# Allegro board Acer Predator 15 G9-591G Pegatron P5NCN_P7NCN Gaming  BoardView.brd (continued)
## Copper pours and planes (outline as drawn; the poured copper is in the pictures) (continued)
N126075660 on BOTTOM (solid shape): 181.52,43.07 182.2,42.39 182.21,42.39 182.27,42.33 186.3,42.33 186.73,41.91 186.73,40.97 182.43,40.97 181.9,41.5 183.56,41.5 183.57,41.44 183.58,41.39 183.6,41.33 183.63,41.29 183.66,41.24 183.7,41.2 183.75,41.17 183.8,41.14 183.85,41.13 183.91,41.12 183.96,41.11 184.02,41.12 184.07,41.13 184.12,41.16 184.17,41.19 184.21,41.22 184.25,41.26 184.28,41.31 184.3,41.36 184.32,41.41 184.33,41.47 184.33,41.52 184.32,41.58 184.3,41.63 184.28,41.68 184.25,41.73 184.21,41.77 184.17,41.81 184.12,41.84 184.07,41.86 184.02,41.87 183.96,41.88 183.91,41.88 183.85,41.87 183.8,41.85 183.75,41.82 183.7,41.79 183.66,41.75 183.63,41.71 183.6,41.66 183.58,41.61 183.57,41.55 183.56,41.5 181.9,41.5 181.51,41.89 181.35,41.91 181.34,42.06 181.34,42.23 181.24,42.33 181.24,42.37 181.19,42.41 181.19,43.06 181.29,43.16 181.43,43.16
N126076879 on IN2 (solid shape): outline of 693 points within 170.18,39.03 182.17,43.76
N126273757 on TOP (solid shape): 24.71,133.71 24.71,133.29 24.68,133.26 23.07,133.26 22.98,133.35 22.98,133.77 23.06,133.85 24.57,133.85
N126612092 on TOP (solid shape): 241.11,89.97 241.11,89.11 241.2,89.02 242.77,89.02 242.82,88.97 242.82,88.17 242.7,88.04 239.84,88.04 239.5,88.38 239.5,89.83 239.79,90.13 240.94,90.13
N126721746 on BOTTOM (solid shape): 22.01,135.27 22.24,135.17 22.47,135.27 22.66,135.27 22.8,135.18 22.97,135.18 22.99,135.19 23.17,135.02 23.17,134.76 22.91,134.51 21.37,134.51 21.3,134.58 21.3,134.8 21.66,135.17 21.68,135.17 21.76,135.21 21.83,135.27
N126721910 on BOTTOM (solid shape): 22.91,135.68 22.97,135.61 23.04,135.56 23.04,135.4 22.95,135.31 22.89,135.3 22.84,135.3 22.56,135.44 22.28,135.3 22.24,135.3 22.19,135.3 21.91,135.44 21.63,135.3 21.54,135.3 21.3,135.05 20.83,135.05 20.75,135.14 20.75,135.43 21,135.68
N129634919 on BOTTOM (solid shape): 155.92,108.7 155.92,107.52 155.81,107.41 155.63,107.41 155.63,107.41 154.48,107.41 154.27,107.62 154.27,108.92 154.34,108.98 155.64,108.98
N129635970 on TOP (solid shape): 147.12,94.73 147.12,94.25 147.25,94.12 147.25,92.86 147.02,92.63 147.02,91.74 146.94,91.66 146.58,91.66 146.35,91.89 146.35,94.54 146.61,94.8 147.05,94.8
N129637628 on TOP (solid shape): 145.37,98.11 145.37,96.14 145.34,96.11 144.91,96.11 144.83,96.19 144.83,96.96 144.2,97.6 144.2,98.14 144.28,98.23 145.26,98.23
N129637680 on TOP (solid shape): 146.86,99.04 146.86,99.03 147.24,98.65 147.24,96.23 147.12,96.11 146.61,96.11 146.61,98.26 146.13,98.75 145.22,98.75 145.22,99.31 145.27,99.36 146.55,99.36
N129962530 on TOP (solid shape): 13.18,72.6 13.96,72.6 14.38,72.18 15,72.18 15.15,72.03 15.15,71.79 15,71.63 14.69,71.63 14.63,71.64 14.57,71.63 14.29,71.63 13.91,72.01 13.09,72.01 11.69,73.4 11.69,73.5 11.94,73.75 12.03,73.75
N129963384 on IN2 (solid shape): outline of 135 points within 15.55,64.76 18.14,67.71
N129963392 on TOP (solid shape): 18.82,66.95 18.82,66.34 18.78,66.29 18.78,65.78 18.62,65.51 18.71,65.22 18.73,65.15 18.71,65.08 18.67,65.03 18.64,64.97 18.64,64.09 19.41,64.53 20.12,64.53 20.13,64.5 20.71,64.37 20.72,64.96 20.68,65.04 20.71,65.11 20.83,65.24 20.83,65.32 20.84,65.33 20.85,65.44 20.84,65.54 20.83,65.55 20.83,65.65 20.59,65.89 20.59,66.97 20.76,66.97 20.81,66.91 20.81,66.25 21.33,65.73 21.33,61.63 20.88,61.18 17.49,61.18 17.49,64.14 17.68,64.14 18.28,64.74 18.28,65.68 18.53,65.94 18.53,66.27 18.6,66.34 18.6,66.91 18.66,66.97 18.8,66.97
N136259332 on TOP (solid shape): 249.83,41.6 249.83,40.2 249.48,39.84 247.6,39.84 246.71,38.96 246.71,38.3 246.63,38.22 246.46,38.22 246.38,38.3 246.38,38.32 246.32,38.51 246.14,38.6 246.12,38.6 246.08,38.65 246.08,38.89 246.09,38.9 246.09,39.22 246.43,39.83 246.43,41.52 246.58,41.67 249.76,41.67
N137261398 on TOP (solid shape): 251.8,82.99 252.64,82.99 252.86,82.77 252.86,80.76 252.65,80.56 250.37,80.56 250.34,80.59 247.6,80.59 247.19,80.99 247.19,81.75 247.44,82.01 250.34,82.01 250.5,82.17 250.54,82.19 250.58,82.17 251.12,82.17 251.12,82.71 251.1,82.75 251.12,82.78 251.33,83 251.79,83
N138435047 on TOP (solid shape): 186.41,81.27 186.41,80.46 187,79.87 187,79.09 186.94,79.03 185.34,79.03 185.17,79.21 185.17,81.19 185.29,81.32 186.36,81.32
N138949618 on BOTTOM (solid shape): 45.77,170.65 45.77,169.94 45.64,169.81 43.74,169.81 43.61,169.94 43.61,170.45 43.61,170.45 43.61,171.04 44.07,171.49 44.93,171.49
N138973270 on BOTTOM (solid shape): 32.31,169.69 31.73,169.11 30.84,169.11 30.67,169.27 30.67,169.68 30.66,169.69 30.66,170.96 32.31,170.96
N138993942 on TOP (solid shape): 63.55,164.43 63.55,163.29 63.3,163.03 61.52,163.03 61.49,163.06 60.99,163.06 60.78,163.26 60.78,163.95 60.93,164.1 62.59,164.1 63.04,164.56 63.42,164.56
N139012589 on TOP (solid shape): 2.08,157.88 2.46,157.49 3.48,157.49 3.48,156.86 3.35,156.73 1.32,156.73 1.19,156.86 1.19,158.64 1.45,158.89 2.08,158.89
N139027720 on BOTTOM (solid shape): 20.63,165.68 20.63,162.48 20.47,162.32 19.81,162.32 19.74,162.4 19.74,165.11 19.79,165.11 19.91,165.24 19.91,166.01 19.99,166.08 20.22,166.08
N139084693 on BOTTOM (solid shape): 68.31,171.59 68.31,169.79 68.35,169.75 68.35,169.25 68.26,169.15 67.9,169.15 67.85,169.21 67.85,169.48 67.84,169.49 67.84,169.79 67.83,169.8 67.83,171.53 67.89,171.59 68.3,171.59
N139090834 on BOTTOM (solid shape): 88.9,170.07 89.21,170.07 89.33,169.94 89.33,169.56 89.21,169.43 87.84,169.43 87.6,169.51 87.37,169.43 86.77,169.43 86.61,169.59 86.61,170.3 86.69,170.38 88.6,170.38
N140034678 on TOP (solid shape): 258.12,107.79 257.61,107.28 255.96,107.28 255.83,107.15 255.83,106.77 253.92,106.77 253.92,107.54 255.83,109.44 257.23,109.44 257.61,109.82 257.61,110.71 258.12,110.71
N145218678 on BOTTOM (solid shape): 224.82,52.85 224.82,51.67 224.96,51.53 224.96,49.31 224.89,49.24 223.68,49.24 223.46,49.46 223.46,50.33 222.67,51.12 222.67,52.75 222.8,52.89 224.78,52.89
N146002641 on TOP (solid shape): 51.38,182.87 51.38,181.89 51.38,181.47 51.38,181.47 51.38,180.8 51.14,180.8 51.13,180.81 51.13,181.9 51.12,181.9 50.88,181.9 50.88,181.9 50.88,180.8 50.64,180.8 50.64,182.83 50.76,182.96 51.29,182.96
N146002641 on BOTTOM (solid shape): 53.23,183.84 52.64,183.84 51.11,182.31 50.82,182.31 50.56,182.57 50.56,184.63 51.87,184.63 51.87,184.63 52.13,184.63 52.18,184.69 53.23,184.69

Small or netless copper shapes (teardrops, artwork), in the pictures only: 4158 on TOP, 5851 on BOTTOM, 1031 on IN1, 539 on IN2, 141 on IN3, 900 on IN4

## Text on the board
BOTTOM: list("[Spacing] BOTTOM" "164.Shape to Route Keepin" "0 MIL [DEFAULT]" "0 MIL" "0.00 MIL" "DRC ERROR CLASS/BOTTOM" "[Shape] Route Keepin/All ((-917.01 -373.7) (9771.34 6936.7))" "[Bottom Shape] GND ((-917.01 -373.7) (9771.34 6944.68))" list(118.110000 -373.700000) nil)@@@list("kelly1_pan" "2015/09/04 14:26:33" nil "P143000035-PC" "n3-p5-p7ncn.20")@@@list("jennifer_hsu" "2015/09/07 11:46:35" nil "P143000039-PC" "n3-p5-p7ncn.20") | list("[Spacing] BOTTOM" "166.Line to SMD Pin" "4.5 MIL [DEFAULT]" "4.4 MIL" "0.10 MIL" "DRC ERROR CLASS/BOTTOM" "[Line] LP9- ((1166.4 6673.51) (1170.9 6752.69))" "[SmdPin] GND (<uTiL>cId3016<uTiL>.2) (1150.0 6724.01)" list(1168.650000 6724.010000) nil)@@@list("kelly1_pan" "2015/09/04 14:26:36" nil "P143000035-PC" "n3-p5-p7ncn.20")@@@list("jennifer_hsu" "2015/09/07 11:46:36" nil "P143000039-PC" "n3-p5-p7ncn.20") | list("[Spacing] BOTTOM" "165.Shape to Route Keepout" "0 MIL [DEFAULT]" "0 MIL" "0.00 MIL" "DRC ERROR CLASS/BOTTOM" "[Shape] Route Keepout/Bottom ((4840.37 356.11) (5175.37 691.11))" "[Bottom Shape] GND ((-917.01 -373.7) (9771.34 6944.68))" list(4906.130000 390.550000) nil)@@@list("kelly1_pan" "2015/09/04 14:26:34" nil "P143000035-PC" "n3-p5-p7ncn.20")@@@list("jennifer_hsu" "2015/09/07 11:46:35" nil "P143000039-PC" "n3-p5-p7ncn.20") | list("[Spacing-SameNet] BOTTOM" "168.Line to Shape Same Net" "5 MIL [DEFAULT]" "0 MIL" "5.00 MIL" "DRC ERROR CLASS/BOTTOM" "[Line] GND ((5340.2 1970.8) (5365.89 1975.8))" "[Bottom Shape] GND ((4986.0 1241.89) (6155.0 2348.1))" list(5358.460000 1973.300000) nil)@@@list("kelly1_pan" "2015/09/04 14:26:38" nil "P143000035-PC" "n3-p5-p7ncn.20")@@@list("jennifer_hsu" "2015/09/07 11:46:38" nil "P143000039-PC" "n3-p5-p7ncn.20") | list("[Spacing] BOTTOM" "161.Shape to Route Keepin" "0 MIL [DEFAULT]" "0 MIL" "0.00 MIL" "DRC ERROR CLASS/BOTTOM" "[Shape] Route Keepin/All ((-917.01 -373.7) (9771.34 6936.7))" "[Bottom Shape] GND_LED ((5460.95 5728.54) (7231.95 6039.17))" list(5460.950000 5736.540000) nil)@@@list("kelly1_pan" "2015/09/04 14:26:30" nil "P143000035-PC" "n3-p5-p7ncn.20")@@@list("jennifer_hsu" "2015/09/07 11:46:33" nil "P143000039-PC" "n3-p5-p7ncn.20") | list("[Spacing] BOTTOM" "162.Shape to Route Keepin" "0 MIL [DEFAULT]" "0 MIL" "0.00 MIL" "DRC ERROR CLASS/BOTTOM" "[Shape] Route Keepin/All ((-917.01 -373.7) (9771.34 6936.7))" "[Bottom Shape] LAN_GND ((9292.77 4683.0) (9698.5 5486.88))" list(9332.360000 5367.300000) nil)@@@list("kelly1_pan" "2015/09/04 14:26:31" nil "P143000035-PC" "n3-p5-p7ncn.20")@@@list("jennifer_hsu" "2015/09/07 11:46:33" nil "P143000039-PC" "n3-p5-p7ncn.20") | list("[Spacing] BOTTOM" "163.Shape to Route Keepin" "0 MIL [DEFAULT]" "0 MIL" "0.00 MIL" "DRC ERROR CLASS/BOTTOM" "[Shape] Route Keepin/All ((-917.01 -373.7) (9771.34 6936.7))" "[Bottom Shape] GND ((9278.0 1449.01) (9668.98 2197.11))" list(9367.790000 1452.900000) nil)@@@list("kelly1_pan" "2015/09/04 14:26:32" nil "P143000035-PC" "n3-p5-p7ncn.20")@@@list("jennifer_hsu" "2015/09/07 11:46:34" nil "P143000039-PC" "n3-p5-p7ncn.20") | list("[Spacing] BOTTOM" "167.Shape to Route Keepin" "0 MIL [DEFAULT]" "0 MIL" "0.00 MIL" "DRC ERROR CLASS/BOTTOM" "[Shape] Route Keepin/All ((-917.01 -373.7) (9771.34 6936.7))" "[Bottom Shape] GND ((9336.61 1757.88) (9671.25 2092.52))" list(9668.980000 1757.880000) nil)@@@list("kelly1_pan" "2015/09/04 14:26:37" nil "P143000035-PC" "n3-p5-p7ncn.20")@@@list("jennifer_hsu" "2015/09/07 11:46:37" nil "P143000039-PC" "n3-p5-p7ncn.20")
Ref Des/Silkscreen Bottom: CON5602 | PCB MADE IN | BOT | CON6701 | XDP4400 | CON3600 | H64 | CON5000 | CON6003 | CON1601 | CON1701 | CON5103 | H61 | H66 | CON5102 | JP9401 | JP9400 | CON4400 | H65 | H63 | CON3100 | U7000 | H60 | CON3110 | H69 | H68 | JP8200 | U2000 | JP8901 | REV:2.0 | _DMIC_L | P/N: | P5NCN/P7NCN | CON3104 | CON5001 | CON3700 | JP8105 | CON4402 | P5NCN/P7NCN_DMIC_R BD | JP9302 | JP9301 | CON6000 | CON5300 | H62 | CON6002 | H34 | H33 | CON3400 | CON2800 | H701 | H702 | CON6700 | CON6001 | CON5101 | CON5100 | JP8061 | JP8056 | JP8103 | JP8104 | vendor | 2ND
TOP: list("[Spacing] TOP" "11.Shape to Route Keepout" "0 MIL [DEFAULT]" "0 MIL" "0.00 MIL" "DRC ERROR CLASS/TOP" "[Shape] Route Keepout/Top ((-195.82 1247.95) (60.4 1504.09))" "[Top Shape] GND ((-917.01 -373.69) (9771.72 6944.68))" list(-63.220000 1247.950000) nil)@@@list("kelly1_pan" "2015/09/02 11:47:46" nil "P143000035-PC" "n3-p5-p7ncn.20")@@@list("jennifer_hsu" "2015/09/07 11:44:02" nil "P143000039-PC" "n3-p5-p7ncn.20") | list("[Spacing] TOP" "10.Shape to Route Keepout" "0 MIL [DEFAULT]" "0 MIL" "0.00 MIL" "DRC ERROR CLASS/TOP" "[Shape] Route Keepout/Top ((-195.82 145.51) (60.4 401.69))" "[Top Shape] GND ((-917.01 -373.69) (9771.72 6944.68))" list(-52.150000 400.780000) nil)@@@list("kelly1_pan" "2015/09/02 11:47:45" nil "P143000035-PC" "n3-p5-p7ncn.20")@@@list("jennifer_hsu" "2015/09/07 11:44:02" nil "P143000039-PC" "n3-p5-p7ncn.20") | list("[Spacing] TOP" "9.Shape to Route Keepin" "0 MIL [DEFAULT]" "0 MIL" "0.00 MIL" "DRC ERROR CLASS/TOP" "[Shape] Route Keepin/All ((-917.01 -373.7) (9771.34 6936.7))" "[Top Shape] GND ((-917.01 -373.69) (9771.72 6944.68))" list(137.480000 381.890000) nil)@@@list("kelly1_pan" "2015/09/02 11:47:44" nil "P143000035-PC" "n3-p5-p7ncn.20")@@@list("jennifer_hsu" "2015/09/07 11:44:01" nil "P143000039-PC" "n3-p5-p7ncn.20") | list("[Spacing] TOP" "15.SMD Pin to SMD Pin Same Net" "3 MIL [DEFAULT]" "OVERLAP" "" "DRC ERROR CLASS/TOP" "[SmdPin] +VCORE (<uTiL>cId1632<uTiL>.2) (489.09 6106.89)" "[SmdPin] +VCORE (<uTiL>cId3931<uTiL>.2) (442.2 6143.49)" list(442.590000 6130.990000) nil)@@@list("kelly1_pan" "2015/09/02 11:47:50" nil "P143000035-PC" "n3-p5-p7ncn.20")@@@list("jennifer_hsu" "2015/09/07 11:44:06" nil "P143000039-PC" "n3-p5-p7ncn.20") | list("[Spacing] TOP" "4.Shape to Route Keepout" "0 MIL [DEFAULT]" "0 MIL" "0.00 MIL" "DRC ERROR CLASS/TOP" "[Shape] Route Keepout/Top ((3271.29 2635.46) (3567.29 2931.46))" "[Top Shape] GND ((3336.7 2521.89) (4319.2 3000.94))" list(3345.800000 2654.990000) nil)@@@list("kelly1_pan" "2015/09/02 11:47:41" nil "P143000035-PC" "n3-p5-p7ncn.20")@@@list("jennifer_hsu" "2015/09/07 11:43:57" nil "P143000039-PC" "n3-p5-p7ncn.20") | list("[Spacing] TOP" "12.SMD Pin to SMD Pin Same Net" "3 MIL [DEFAULT]" "0 MIL" "3.00 MIL" "DRC ERROR CLASS/TOP" "[SmdPin] +2.5VO (<uTiL>cId3914<uTiL>.2) (3467.0 2161.89)" "[SmdPin] +2.5VO (<uTiL>cId3915<uTiL>.2) (3450.0 2173.89)" list(3462.500000 2171.890000) nil)@@@list("kelly1_pan" "2015/09/02 11:47:47" nil "P143000035-PC" "n3-p5-p7ncn.20")@@@list("jennifer_hsu" "2015/09/07 11:44:03" nil "P143000039-PC" "n3-p5-p7ncn.20") | list("[Spacing] TOP" "13.SMD Pin to SMD Pin Same Net" "3 MIL [DEFAULT]" "0 MIL" "3.00 MIL" "DRC ERROR CLASS/TOP" "[SmdPin] +1.2VO_DDR (<uTiL>cId3922<uTiL>.1) (3671.0 2328.89)" "[SmdPin] +1.2VO_DDR (<uTiL>cId3921<uTiL>.1) (3688.0 2335.89)" list(3683.500000 2328.890000) nil)@@@list("kelly1_pan" "2015/09/02 11:47:48" nil "P143000035-PC" "n3-p5-p7ncn.20")@@@list("jennifer_hsu" "2015/09/07 11:44:04" nil "P143000039-PC" "n3-p5-p7ncn.20") | list("[Spacing] TOP" "14.SMD Pin to SMD Pin Same Net" "3 MIL [DEFAULT]" "OVERLAP" "" "DRC ERROR CLASS/TOP" "[SmdPin] +0.6VO (<uTiL>cId4502<uTiL>.1) (4243.62 1911.89)" "[SmdPin] +0.6VO (<uTiL>cId1706<uTiL>.1) (4256.0 1909.0)" list(4254.620000 1896.500000) nil)@@@list("kelly1_pan" "2015/09/02 11:47:49" nil "P143000035-PC" "n3-p5-p7ncn.20")@@@list("jennifer_hsu" "2015/09/07 11:44:05" nil "P143000039-PC" "n3-p5-p7ncn.20") | list("[Spacing] TOP" "2.Shape to Route Keepin" "0 MIL [DEFAULT]" "0 MIL" "0.00 MIL" "DRC ERROR CLASS/TOP" "[Shape] Route Keepin/All ((-917.01 -373.7) (9771.34 6936.7))" "[Top Shape] GND_LED ((5460.95 5728.54) (7231.95 6031.17))" list(5552.560000 5736.540000) nil)@@@list("kelly1_pan" "2015/09/02 11:47:39" nil "P143000035-PC" "n3-p5-p7ncn.20")@@@list("jennifer_hsu" "2015/09/07 11:43:55" nil "P143000039-PC" "n3-p5-p7ncn.20") | list("[Spacing] TOP" "1.Shape to Route Keepin" "0 MIL [DEFAULT]" "0 MIL" "0.00 MIL" "DRC ERROR CLASS/TOP" "[Shape] Route Keepin/All ((-917.01 -373.7) (9771.34 6936.7))" "[Top Shape] GND_D-MIC R ((6567.24 5303.46) (7357.95 5617.79))" list(6586.610000 5303.470000) nil)@@@list("kelly1_pan" "2015/09/02 11:47:38" nil "P143000035-PC" "n3-p5-p7ncn.20")@@@list("jennifer_hsu" "2015/09/07 11:43:55" nil "P143000039-PC" "n3-p5-p7ncn.20") | list("[Physical] TOP" "94.Pad/Pad Direct Connect" "NOT_ALLOWED [(GND_20)]" "ALL_ALLOWED" "" "DRC ERROR CLASS/TOP" "[ThruPin] GND (<uTiL>cId2974<uTiL>.49) (8093.66 3281.89)" "[SmdPin] GND (<uTiL>cId2974<uTiL>.41) (8035.0 3281.89)" list(8093.660000 3281.890000) nil)@@@list("kelly1_pan" "2015/09/04 14:26:39" nil "P143000035-PC" "n3-p5-p7ncn.20")@@@nil | list("[Spacing] TOP" "3.Shape to Route Keepin" "0 MIL [DEFAULT]" "0 MIL" "0.00 MIL" "DRC ERROR CLASS/TOP" "[Shape] Route Keepin/All ((-917.01 -373.7) (9771.34 6936.7))" "[Top Shape] LAN_GND ((9292.76 4683.0) (9698.5 5486.88))" list(9332.360000 5367.300000) nil)@@@list("kelly1_pan" "2015/09/02 11:47:40" nil "P143000035-PC" "n3-p5-p7ncn.20")@@@list("jennifer_hsu" "2015/09/07 11:43:56" nil "P143000039-PC" "n3-p5-p7ncn.20") | list("[Spacing] TOP" "5.Shape to Route Keepin" "0 MIL [DEFAULT]" "0 MIL" "0.00 MIL" "DRC ERROR CLASS/TOP" "[Shape] Route Keepin/All ((-917.01 -373.7) (9771.34 6936.7))" "[Top Shape] GND ((9319.8 2527.75) (9367.8 2695.57))" list(9367.790000 2691.850000) nil)@@@list("kelly1_pan" "2015/09/02 11:47:42" nil "P143000035-PC" "n3-p5-p7ncn.20")@@@list("jennifer_hsu" "2015/09/07 11:43:58" nil "P143000039-PC" "n3-p5-p7ncn.20") | list("[Spacing] TOP" "8.Shape to Route Keepin" "0 MIL [DEFAULT]" "0 MIL" "0.00 MIL" "DRC ERROR CLASS/TOP" "[Shape] Route Keepin/All ((-917.01 -373.7) (9771.34 6936.7))" "[Top Shape] GND ((9250.3 1449.01) (9668.97 2197.18))" list(9368.830000 1660.590000) nil)@@@list("kelly1_pan" "2015/09/02 11:46:52" nil "P143000035-PC" "n3-p5-p7ncn.20")@@@list("jennifer_hsu" "2015/09/07 11:44:00" nil "P143000039-PC" "n3-p5-p7ncn.20") | list("[Spacing] TOP" "6.Shape to Route Keepout" "0 MIL [DEFAULT]" "0 MIL" "0.00 MIL" "DRC ERROR CLASS/TOP" "[Shape] Route Keepout/All ((-937.01 -393.7) (9791.34 6956.69))" "[Top Shape] GND ((9251.0 2737.09) (9698.51 4686.9))" list(9676.990000 2758.030000) nil)@@@list("kelly1_pan" "2015/09/02 11:47:07" nil "P143000035-PC" "n3-p5-p7ncn.20")@@@list("jennifer_hsu" "2015/09/07 11:43:58" nil "P143000039-PC" "n3-p5-p7ncn.20") | list("[Spacing] TOP" "7.Shape to Route Keepin" "0 MIL [DEFAULT]" "0 MIL" "0.00 MIL" "DRC ERROR CLASS/TOP" "[Shape] Route Keepin/All ((-917.01 -373.7) (9771.34 6936.7))" "[Top Shape] GND ((9251.0 2737.09) (9698.51 4686.9))" list(9688.980000 2770.050000) nil)@@@list("kelly1_pan" "2015/09/02 11:47:08" nil "P143000035-PC" "n3-p5-p7ncn.20")@@@list("jennifer_hsu" "2015/09/07 11:43:59" nil "P143000039-PC" "n3-p5-p7ncn.20")
Ref Des/Silkscreen Top: JP9601 | JP9600 | REV:2.0 | CON1 | P5NCN/P7NCN_LED BD | TOP | JP8802 | JP8801 | JP9300 | JP8806 | JP8059 | JP8060 | CON1600 | CON1700 | JP8055 | JP8054 | CON4500 | CON4301 | JP9500 | JP9501 | JP8304 | JP8303 | JP8301 | JP9000 | JP8300 | JP8202 | JP8902 | JP8400 | PCON700 | CON300 | H301 | CON402 | P5NCN/P7NCN_PWR BOARD | PCB MADE IN | CON400 | PCON702 | JP8109 | JP8102 | JP8108 | JP8106 | JP9303 | JP8100 | JP8101 | JP8110 | JP8111 | JP8800 | JP8803 | H402 | JP8058 | JP8057 | JP8052 | JP8053 | JP8051 | JP8050 | JP9602 | JP8302 | JP9502 | CON302 | JP8804 | JP8805 | JP8107 | CON4601 | CON5501 | CON5500 | CON4800 | CON1201 | JP5601 | H53 | H54 | 2015/9/7 | 2.0/650  mils | P5NCN/P7NCN MAIN BOARD | 1ST
GND1: list("[Spacing] GND1" "29.Thru Pin to Shape" "5 MIL [DEFAULT]" "4.99 MIL" "0.01 MIL" "DRC ERROR CLASS/GND1" "[ThruPin] GND (<uTiL>cId65<uTiL>.50) (-256.51 2263.3)" "[Gnd1 Shape] AGND ((-610.0 2155.0) (-65.0 2696.89))" list(-265.000000 2254.810000) nil)@@@list("kelly1_pan" "2015/09/02 15:29:40" nil "p143000035-pc" "n3-p5-p7ncn.20")@@@list("jennifer_hsu" "2015/09/07 11:44:30" nil "P143000039-PC" "n3-p5-p7ncn.20") | list("[Spacing] GND1" "19.Thru Pin to Shape Same Net" "5 MIL [DEFAULT]" "0 MIL" "5.00 MIL" "DRC ERROR CLASS/GND1" "[ThruPin] GND (<uTiL>cId65<uTiL>.50) (-256.51 2263.3)" "[Gnd1 Shape] GND ((-917.01 -373.7) (9771.34 6936.7))" list(-255.000000 2275.200000) nil)@@@list("kelly1_pan" "2015/09/02 15:29:31" nil "p143000035-pc" "n3-p5-p7ncn.20")@@@list("jennifer_hsu" "2015/09/07 11:44:09" nil "P143000039-PC" "n3-p5-p7ncn.20") | list("[Spacing] GND1" "20.Thru Pin to Shape Same Net" "5 MIL [DEFAULT]" "0 MIL" "5.00 MIL" "DRC ERROR CLASS/GND1" "[ThruPin] GND (<uTiL>cId65<uTiL>.51) (-256.51 2422.28)" "[Gnd1 Shape] GND ((-917.01 -373.7) (9771.34 6936.7))" list(-249.320000 2431.890000) nil)@@@list("kelly1_pan" "2015/09/02 15:29:32" nil "p143000035-pc" "n3-p5-p7ncn.20")@@@list("jennifer_hsu" "2015/09/07 11:44:09" nil "P143000039-PC" "n3-p5-p7ncn.20") | list("[Spacing] GND1" "22.Shape to Route Keepout" "0 MIL [DEFAULT]" "0 MIL" "0.00 MIL" "DRC ERROR CLASS/GND1" "[Shape] Route Keepout/All ((-133.59 333.73) (-56.95 410.36))" "[Gnd1 Shape] GND ((-917.01 -373.7) (9771.34 6936.7))" list(-95.270000 410.360000) nil)@@@list("kelly1_pan" "2015/09/02 15:29:34" nil "p143000035-pc" "n3-p5-p7ncn.20")@@@list("jennifer_hsu" "2015/09/07 11:44:11" nil "P143000039-PC" "n3-p5-p7ncn.20") | list("[Spacing] GND1" "21.Shape to Route Keepout" "0 MIL [DEFAULT]" "0 MIL" "0.00 MIL" "DRC ERROR CLASS/GND1" "[Shape] Route Keepout/All ((-123.21 218.12) (-12.21 329.12))" "[Gnd1 Shape] GND ((-917.01 -373.7) (9771.34 6936.7))" list(-67.710000 329.120000) nil)@@@list("kelly1_pan" "2015/09/02 15:29:33" nil "p143000035-pc" "n3-p5-p7ncn.20")@@@list("jennifer_hsu" "2015/09/07 11:44:10" nil "P143000039-PC" "n3-p5-p7ncn.20") | list("[Spacing] GND1" "26.Shape to Route Keepout" "0 MIL [DEFAULT]" "0 MIL" "0.00 MIL" "DRC ERROR CLASS/GND1" "[Shape] Route Keepout/All ((1831.32 6634.59) (1885.01 6688.27))" "[Gnd1 Shape] GND ((-917.01 -373.7) (9771.34 6936.7))" list(1885.010000 6661.430000) nil)@@@list("kelly1_pan" "2015/09/02 15:29:37" nil "p143000035-pc" "n3-p5-p7ncn.20")@@@list("jennifer_hsu" "2015/09/07 11:44:13" nil "P143000039-PC" "n3-p5-p7ncn.20") | list("[Spacing] GND1" "27.Shape to Route Keepout" "0 MIL [DEFAULT]" "0 MIL" "0.00 MIL" "DRC ERROR CLASS/GND1" "[Shape] Route Keepout/All ((3022.0 6798.93) (3081.62 6858.55))" "[Gnd1 Shape] GND ((-917.01 -373.7) (9771.34 6936.7))" list(3051.810000 6858.550000) nil)@@@list("kelly1_pan" "2015/09/02 15:29:37" nil "p143000035-pc" "n3-p5-p7ncn.20")@@@list("jennifer_hsu" "2015/09/07 11:44:14" nil "P143000039-PC" "n3-p5-p7ncn.20") | list("[Spacing] GND1" "16.Shape to Route Keepin" "0 MIL [DEFAULT]" "0 MIL" "0.00 MIL" "DRC ERROR CLASS/GND1" "[Shape] Route Keepin/All ((-917.01 -373.7) (9771.34 6936.7))" "[Gnd1 Shape] GND_D-MIC R ((6567.24 5303.47) (7357.95 5617.8))" list(6869.960000 5617.800000) nil)@@@list("kelly1_pan" "2015/09/02 15:32:45" nil "P143000035-PC" "n3-p5-p7ncn.20")@@@list("jennifer_hsu" "2015/09/07 11:44:06" nil "P143000039-PC" "n3-p5-p7ncn.20") | list("[Spacing] GND1" "24.Shape to Route Keepout" "0 MIL [DEFAULT]" "0 MIL" "0.00 MIL" "DRC ERROR CLASS/GND1" "[Shape] Route Keepout/All ((8281.64 3112.35) (8348.26 3178.97))" "[Gnd1 Shape] GND ((-917.01 -373.7) (9771.34 6936.7))" list(8348.260000 3145.660000) nil)@@@list("kelly1_pan" "2015/09/02 15:29:35" nil "p143000035-pc" "n3-p5-p7ncn.20")@@@list("jennifer_hsu" "2015/09/07 11:44:12" nil "P143000039-PC" "n3-p5-p7ncn.20") | list("[Spacing] GND1" "23.Shape to Route Keepout" "0 MIL [DEFAULT]" "0 MIL" "0.00 MIL" "DRC ERROR CLASS/GND1" "[Shape] Route Keepout/All ((8396.75 1692.04) (8469.37 1764.66))" "[Gnd1 Shape] GND ((-917.01 -373.7) (9771.34 6936.7))" list(8469.370000 1728.350000) nil)@@@list("kelly1_pan" "2015/09/02 15:29:34" nil "p143000035-pc" "n3-p5-p7ncn.20")@@@list("jennifer_hsu" "2015/09/07 11:44:11" nil "P143000039-PC" "n3-p5-p7ncn.20") | list("[Spacing] GND1" "25.Shape to Route Keepout" "0 MIL [DEFAULT]" "0 MIL" "0.00 MIL" "DRC ERROR CLASS/GND1" "[Shape] Route Keepout/All ((8775.0 4660.0) (9725.0 5506.4))" "[Gnd1 Shape] GND ((-917.01 -373.7) (9771.34 6936.7))" list(9252.800000 4689.950000) nil)@@@list("kelly1_pan" "2015/09/02 15:29:36" nil "p143000035-pc" "n3-p5-p7ncn.20")@@@list("jennifer_hsu" "2015/09/07 11:44:13" nil "P143000039-PC" "n3-p5-p7ncn.20") | list("[Spacing] GND1" "17.Shape to Route Keepout" "0 MIL [DEFAULT]" "0 MIL" "0.00 MIL" "DRC ERROR CLASS/GND1" "[Shape] Route Keepout/All ((8775.0 4660.0) (9725.0 5506.4))" "[Gnd1 Shape] LAN_GND ((8795.0 4680.0) (9698.5 5487.0))" list(9289.360000 4680.000000) nil)@@@list("kelly1_pan" "2015/09/02 15:29:29" nil "p143000035-pc" "n3-p5-p7ncn.20")@@@list("jennifer_hsu" "2015/09/07 11:44:07" nil "P143000039-PC" "n3-p5-p7ncn.20") | list("[Spacing] GND1" "18.Shape to Route Keepin" "0 MIL [DEFAULT]" "0 MIL" "0.00 MIL" "DRC ERROR CLASS/GND1" "[Shape] Route Keepin/All ((-917.01 -373.7) (9771.34 6936.7))" "[Gnd1 Shape] LAN_GND ((8795.0 4680.0) (9698.5 5487.0))" list(9386.640000 5421.580000) nil)@@@list("kelly1_pan" "2015/09/02 15:29:30" nil "p143000035-pc" "n3-p5-p7ncn.20")@@@list("jennifer_hsu" "2015/09/07 11:44:08" nil "P143000039-PC" "n3-p5-p7ncn.20") | list("[Spacing] GND1" "28.Shape to Route Keepin" "0 MIL [DEFAULT]" "0 MIL" "0.00 MIL" "DRC ERROR CLASS/GND1" "[Shape] Route Keepin/All ((-917.01 -373.7) (9771.34 6936.7))" "[Gnd1 Shape] GND ((-917.01 -373.7) (9771.34 6936.7))" list(9433.500000 4571.180000) nil)@@@list("kelly1_pan" "2015/09/02 15:29:38" nil "p143000035-pc" "n3-p5-p7ncn.20")@@@list("jennifer_hsu" "2015/09/07 11:44:14" nil "P143000039-PC" "n3-p5-p7ncn.20")
IN1: list("[Spacing] IN1" "35.Shape to Route Keepin" "0 MIL [DEFAULT]" "0 MIL" "0.00 MIL" "DRC ERROR CLASS/IN1" "[Shape] Route Keepin/All ((-917.01 -373.7) (9771.34 6936.7))" "[In1 Shape] GND ((-137.47 -373.69) (9771.34 1219.0))" list(137.480000 381.890000) nil)@@@list("kelly1_pan" "2015/09/02 15:32:58" nil "P143000035-PC" "n3-p5-p7ncn.20")@@@list("jennifer_hsu" "2015/09/07 11:44:35" nil "P143000039-PC" "n3-p5-p7ncn.20") | list("[Spacing] IN1" "30.Shape to Route Keepin" "0 MIL [DEFAULT]" "0 MIL" "0.00 MIL" "DRC ERROR CLASS/IN1" "[Shape] Route Keepin/All ((-917.01 -373.7) (9771.34 6936.7))" "[In1 Shape] GND_LED ((5460.94 5736.53) (7231.96 6031.18))" list(6260.100000 5736.540000) nil)@@@list("kelly1_pan" "2015/09/02 15:32:47" nil "P143000035-PC" "n3-p5-p7ncn.20")@@@list("jennifer_hsu" "2015/09/07 11:44:31" nil "P143000039-PC" "n3-p5-p7ncn.20") | list("[Spacing] IN1" "36.Shape to Route Keepin" "0 MIL [DEFAULT]" "0 MIL" "0.00 MIL" "DRC ERROR CLASS/IN1" "[Shape] Route Keepin/All ((-917.01 -373.7) (9771.34 6936.7))" "[In1 Shape] GND ((-917.0 1327.0) (9698.51 6936.7))" list(6742.230000 2896.930000) nil)@@@list("kelly1_pan" "2015/09/02 15:32:59" nil "P143000035-PC" "n3-p5-p7ncn.20")@@@list("jennifer_hsu" "2015/09/07 11:44:36" nil "P143000039-PC" "n3-p5-p7ncn.20") | list("[Spacing] IN1" "31.Shape to Route Keepin" "0 MIL [DEFAULT]" "0 MIL" "0.00 MIL" "DRC ERROR CLASS/IN1" "[Shape] Route Keepin/All ((-917.01 -373.7) (9771.34 6936.7))" "[In1 Shape] LAN_GND ((9292.77 4680.51) (9698.51 5486.88))" list(9332.360000 5367.300000) nil)@@@list("kelly1_pan" "2015/09/02 15:32:48" nil "P143000035-PC" "n3-p5-p7ncn.20")@@@list("jennifer_hsu" "2015/09/07 11:44:32" nil "P143000039-PC" "n3-p5-p7ncn.20") | list("[Spacing] IN1" "34.Shape to Route Keepin" "0 MIL [DEFAULT]" "0 MIL" "0.00 MIL" "DRC ERROR CLASS/IN1" "[Shape] Route Keepin/All ((-917.01 -373.7) (9771.34 6936.7))" "[In1 Shape] GND ((9268.0 1129.54) (9367.8 1626.71))" list(9367.790000 1396.470000) nil)@@@list("kelly1_pan" "2015/09/02 15:32:49" nil "P143000035-PC" "n3-p5-p7ncn.20")@@@list("jennifer_hsu" "2015/09/07 11:44:35" nil "P143000039-PC" "n3-p5-p7ncn.20") | list("[Spacing] IN1" "32.Shape to Route Keepin" "0 MIL [DEFAULT]" "0 MIL" "0.00 MIL" "DRC ERROR CLASS/IN1" "[Shape] Route Keepin/All ((-917.01 -373.7) (9771.34 6936.7))" "[In1 Shape] GND ((9210.0 1653.11) (9698.5 3131.17))" list(9368.840000 1660.640000) nil)@@@list("kelly1_pan" "2015/09/02 15:32:50" nil "P143000035-PC" "n3-p5-p7ncn.20")@@@list("jennifer_hsu" "2015/09/07 11:44:33" nil "P143000039-PC" "n3-p5-p7ncn.20") | list("[Spacing] IN1" "33.Shape to Route Keepout" "0 MIL [DEFAULT]" "0 MIL" "0.00 MIL" "DRC ERROR CLASS/IN1" "[Shape] Route Keepout/All ((-937.01 -393.7) (9791.34 6956.69))" "[In1 Shape] GND ((9210.0 1653.11) (9698.5 3131.17))" list(9676.990000 2758.020000) nil)@@@list("kelly1_pan" "2015/09/02 15:32:57" nil "P143000035-PC" "n3-p5-p7ncn.20")@@@list("jennifer_hsu" "2015/09/07 11:44:34" nil "P143000039-PC" "n3-p5-p7ncn.20") | list("[Spacing] IN1" "38.Shape to Route Keepout" "0 MIL [DEFAULT]" "0 MIL" "0.00 MIL" "DRC ERROR CLASS/IN1" "[Shape] Route Keepout/All ((9655.0 4660.5) (9762.0 4680.5))" "[In1 Shape] GND ((-917.0 1327.0) (9698.51 6936.7))" list(9678.600000 4660.500000) nil)@@@list("kelly1_pan" "2015/09/02 15:33:01" nil "P143000035-PC" "n3-p5-p7ncn.20")@@@list("jennifer_hsu" "2015/09/07 11:44:38" nil "P143000039-PC" "n3-p5-p7ncn.20") | list("[Spacing] IN1" "37.Shape to Route Keepout" "0 MIL [DEFAULT]" "0 MIL" "0.00 MIL" "DRC ERROR CLASS/IN1" "[Shape] Route Keepout/All ((8775.0 4660.0) (9725.0 5506.4))" "[In1 Shape] GND ((-917.0 1327.0) (9698.51 6936.7))" list(9678.600000 4660.000000) nil)@@@list("kelly1_pan" "2015/09/02 15:33:00" nil "P143000035-PC" "n3-p5-p7ncn.20")@@@list("jennifer_hsu" "2015/09/07 11:44:37" nil "P143000039-PC" "n3-p5-p7ncn.20")
GND2: list("[Spacing] GND2" "75.Shape to Route Keepout" "0 MIL [DEFAULT]" "0 MIL" "0.00 MIL" "DRC ERROR CLASS/GND2" "[Shape] Route Keepout/All ((-831.77 4457.88) (-768.15 4521.5))" "[Gnd2 Shape] +AC_BAT_SYS ((-885.0 1165.0) (230.0 6905.0))" list(-830.000000 4500.150000) nil)@@@list("kelly1_pan" "2015/09/02 15:36:58" nil "P143000035-PC" "n3-p5-p7ncn.20")@@@list("jennifer_hsu" "2015/09/07 11:45:20" nil "P143000039-PC" "n3-p5-p7ncn.20") | list("[Spacing] GND2" "71.Shape to Route Keepout" "0 MIL [DEFAULT]" "0 MIL" "0.00 MIL" "DRC ERROR CLASS/GND2" "[Shape] Route Keepout/All ((-831.77 4457.88) (-768.15 4521.5))" "[Gnd2 Shape] GND ((-917.01 -373.7) (9771.34 6936.7))" list(-768.150000 4489.690000) nil)@@@list("kelly1_pan" "2015/09/02 15:33:33" nil "P143000035-PC" "n3-p5-p7ncn.20")@@@list("jennifer_hsu" "2015/09/07 11:45:08" nil "P143000039-PC" "n3-p5-p7ncn.20") | list("[Spacing] GND2" "85.Thru Pin to Shape" "5 MIL [DEFAULT]" "4.99 MIL" "0.01 MIL" "DRC ERROR CLASS/GND2" "[ThruPin] GND (<uTiL>cId65<uTiL>.50) (-256.51 2263.3)" "[Gnd2 Shape] AGND ((-610.0 2155.0) (-65.0 2696.89))" list(-265.000000 2254.810000) nil)@@@list("kelly1_pan" "2015/09/04 14:25:19" nil "P143000035-PC" "n3-p5-p7ncn.20")@@@list("jennifer_hsu" "2015/09/07 11:45:30" nil "P143000039-PC" "n3-p5-p7ncn.20") | list("[Spacing] GND2" "42.Thru Pin to Shape Same Net" "5 MIL [DEFAULT]" "0 MIL" "5.00 MIL" "DRC ERROR CLASS/GND2" "[ThruPin] GND (<uTiL>cId65<uTiL>.50) (-256.51 2263.3)" "[Gnd2 Shape] GND ((-917.01 -373.7) (9771.34 6936.7))" list(-255.000000 2275.200000) nil)@@@list("kelly1_pan" "2015/09/02 15:33:05" nil "P143000035-PC" "n3-p5-p7ncn.20")@@@list("jennifer_hsu" "2015/09/07 11:44:40" nil "P143000039-PC" "n3-p5-p7ncn.20") | list("[Spacing] GND2" "43.Thru Pin to Shape Same Net" "5 MIL [DEFAULT]" "0 MIL" "5.00 MIL" "DRC ERROR CLASS/GND2" "[ThruPin] GND (<uTiL>cId65<uTiL>.51) (-256.51 2422.28)" "[Gnd2 Shape] GND ((-917.01 -373.7) (9771.34 6936.7))" list(-249.320000 2431.890000) nil)@@@list("kelly1_pan" "2015/09/02 15:33:06" nil "P143000035-PC" "n3-p5-p7ncn.20")@@@list("jennifer_hsu" "2015/09/07 11:44:41" nil "P143000039-PC" "n3-p5-p7ncn.20") | list("[Spacing] GND2" "59.Shape to Route Keepout" "0 MIL [DEFAULT]" "0 MIL" "0.00 MIL" "DRC ERROR CLASS/GND2" "[Shape] Route Keepout/All ((-133.59 333.73) (-56.95 410.36))" "[Gnd2 Shape] GND ((-917.01 -373.7) (9771.34 6936.7))" list(-95.270000 410.360000) nil)@@@list("kelly1_pan" "2015/09/02 15:33:22" nil "P143000035-PC" "n3-p5-p7ncn.20")@@@list("jennifer_hsu" "2015/09/07 11:44:59" nil "P143000039-PC" "n3-p5-p7ncn.20") | list("[Spacing] GND2" "62.Shape to Route Keepout" "0 MIL [DEFAULT]" "0 MIL" "0.00 MIL" "DRC ERROR CLASS/GND2" "[Shape] Route Keepout/All ((-123.21 1320.48) (-12.21 1431.48))" "[Gnd2 Shape] GND ((-917.01 -373.7) (9771.34 6936.7))" list(-67.710000 1431.480000) nil)@@@list("kelly1_pan" "2015/09/02 15:33:25" nil "P143000035-PC" "n3-p5-p7ncn.20")@@@list("jennifer_hsu" "2015/09/07 11:45:02" nil "P143000039-PC" "n3-p5-p7ncn.20") | list("[Spacing] GND2" "58.Shape to Route Keepout" "0 MIL [DEFAULT]" "0 MIL" "0.00 MIL" "DRC ERROR CLASS/GND2" "[Shape] Route Keepout/All ((-123.21 218.12) (-12.21 329.12))" "[Gnd2 Shape] GND ((-917.01 -373.7) (9771.34 6936.7))" list(-67.710000 329.120000) nil)@@@list("kelly1_pan" "2015/09/02 15:33:21" nil "P143000035-PC" "n3-p5-p7ncn.20")@@@list("jennifer_hsu" "2015/09/07 11:44:59" nil "P143000039-PC" "n3-p5-p7ncn.20") | list("[Spacing] GND2" "67.Shape to Route Keepout" "0 MIL [DEFAULT]" "0 MIL" "0.00 MIL" "DRC ERROR CLASS/GND2" "[Shape] Route Keepout/All ((226.22 2446.7) (309.22 2529.7))" "[Gnd2 Shape] GND ((-917.01 -373.7) (9771.34 6936.7))" list(226.220000 2488.200000) nil)@@@list("kelly1_pan" "2015/09/02 15:33:29" nil "P143000035-PC" "n3-p5-p7ncn.20")@@@list("jennifer_hsu" "2015/09/07 11:45:05" nil "P143000039-PC" "n3-p5-p7ncn.20") | list("[Spacing] GND2" "76.Shape to Thru Via" "5 MIL [DEFAULT]" "0 MIL" "5.00 MIL" "DRC ERROR CLASS/GND2" "[ThruVia] GND (VIA30D18A40) (249.0 5774.89)" "[Gnd2 Shape] +VCCGT ((-60.0 4840.0) (695.0 5765.0))" list(260.280000 5765.000000) nil)@@@list("kelly1_pan" "2015/09/04 14:30:14" nil "P143000035-PC" "n3-p5-p7ncn.20")@@@list("jennifer_hsu" "2015/09/07 11:45:21" nil "P143000039-PC" "n3-p5-p7ncn.20") | list("[Spacing] GND2" "52.Shape to Thru Via Same Net" "5 MIL [DEFAULT]" "0 MIL" "5.00 MIL" "DRC ERROR CLASS/GND2" "[ThruVia] GND (VIA30D18A40) (249.0 5774.89)" "[Gnd2 Shape] GND ((-917.01 -373.7) (9771.34 6936.7))" list(264.000000 5775.000000) nil)@@@list("kelly1_pan" "2015/09/02 15:33:15" nil "P143000035-PC" "n3-p5-p7ncn.20")@@@list("jennifer_hsu" "2015/09/07 11:44:53" nil "P143000039-PC" "n3-p5-p7ncn.20") | list("[Spacing] GND2" "78.Shape to Thru Via" "5 MIL [DEFAULT]" "0 MIL" "5.00 MIL" "DRC ERROR CLASS/GND2" "[ThruVia] GND (VIA30D18A40) (284.0 5774.89)" "[Gnd2 Shape] +VCCGT ((-60.0 4840.0) (695.0 5765.0))" list(295.280000 5765.000000) nil)@@@list("kelly1_pan" "2015/09/04 14:25:14" nil "P143000035-PC" "n3-p5-p7ncn.20")@@@list("jennifer_hsu" "2015/09/07 11:45:22" nil "P143000039-PC" "n3-p5-p7ncn.20") | list("[Spacing] GND2" "54.Shape to Thru Via Same Net" "5 MIL [DEFAULT]" "0 MIL" "5.00 MIL" "DRC ERROR CLASS/GND2" "[ThruVia] GND (VIA30D18A40) (284.0 5774.89)" "[Gnd2 Shape] GND ((-917.01 -373.7) (9771.34 6936.7))" list(299.000000 5775.000000) nil)@@@list("kelly1_pan" "2015/09/02 15:33:17" nil "P143000035-PC" "n3-p5-p7ncn.20")@@@list("jennifer_hsu" "2015/09/07 11:44:55" nil "P143000039-PC" "n3-p5-p7ncn.20") | list("[Spacing] GND2" "64.Shape to Route Keepout" "0 MIL [DEFAULT]" "0 MIL" "0.00 MIL" "DRC ERROR CLASS/GND2" "[Shape] Route Keepout/All ((226.22 1974.25) (309.22 2057.25))" "[Gnd2 Shape] GND ((-917.01 -373.7) (9771.34 6936.7))" list(306.120000 2000.020000) nil)@@@list("kelly1_pan" "2015/09/02 15:33:27" nil "P143000035-PC" "n3-p5-p7ncn.20")@@@list("jennifer_hsu" "2015/09/07 11:45:03" nil "P143000039-PC" "n3-p5-p7ncn.20") | list("[Spacing] GND2" "77.Shape to Thru Via" "5 MIL [DEFAULT]" "0 MIL" "5.00 MIL" "DRC ERROR CLASS/GND2" "[ThruVia] GND (VIA30D18A40) (319.0 5774.89)" "[Gnd2 Shape] +VCCGT ((-60.0 4840.0) (695.0 5765.0))" list(330.280000 5765.000000) nil)@@@list("kelly1_pan" "2015/09/04 14:25:13" nil "P143000035-PC" "n3-p5-p7ncn.20")@@@list("jennifer_hsu" "2015/09/07 11:45:21" nil "P143000039-PC" "n3-p5-p7ncn.20") | list("[Spacing] GND2" "53.Shape to Thru Via Same Net" "5 MIL [DEFAULT]" "0 MIL" "5.00 MIL" "DRC ERROR CLASS/GND2" "[ThruVia] GND (VIA30D18A40) (319.0 5774.89)" "[Gnd2 Shape] GND ((-917.01 -373.7) (9771.34 6936.7))" list(334.000000 5775.000000) nil)@@@list("kelly1_pan" "2015/09/02 15:33:16" nil "P143000035-PC" "n3-p5-p7ncn.20")@@@list("jennifer_hsu" "2015/09/07 11:44:54" nil "P143000039-PC" "n3-p5-p7ncn.20") | list("[Spacing] GND2" "65.Shape to Route Keepout" "0 MIL [DEFAULT]" "0 MIL" "0.00 MIL" "DRC ERROR CLASS/GND2" "[Shape] Route Keepout/All ((303.16 1972.45) (389.78 2059.07))" "[Gnd2 Shape] GND ((-917.01 -373.7) (9771.34 6936.7))" list(346.470000 2059.070000) nil)@@@list("kelly1_pan" "2015/09/02 15:33:27" nil "P143000035-PC" "n3-p5-p7ncn.20")@@@list("jennifer_hsu" "2015/09/07 11:45:04" nil "P143000039-PC" "n3-p5-p7ncn.20") | list("[Spacing] GND2" "68.Shape to Route Keepout" "0 MIL [DEFAULT]" "0 MIL" "0.00 MIL" "DRC ERROR CLASS/GND2" "[Shape] Route Keepout/All ((304.96 2446.68) (387.96 2529.68))" "[Gnd2 Shape] GND ((-917.01 -373.7) (9771.34 6936.7))" list(387.960000 2488.180000) nil)@@@list("kelly1_pan" "2015/09/02 15:33:30" nil "P143000035-PC" "n3-p5-p7ncn.20")@@@list("jennifer_hsu" "2015/09/07 11:45:06" nil "P143000039-PC" "n3-p5-p7ncn.20") | list("[Spacing] GND2" "61.Shape to Route Keepout" "0 MIL [DEFAULT]" "0 MIL" "0.00 MIL" "DRC ERROR CLASS/GND2" "[Shape] Route Keepout/All ((568.61 1119.8) (628.23 1179.42))" "[Gnd2 Shape] GND ((-917.01 -373.7) (9771.34 6936.7))" list(568.610000 1149.610000) nil)@@@list("kelly1_pan" "2015/09/02 15:33:24" nil "P143000035-PC" "n3-p5-p7ncn.20")@@@list("jennifer_hsu" "2015/09/07 11:45:01" nil "P143000039-PC" "n3-p5-p7ncn.20") | list("[Spacing] GND2" "89.Shape to Thru Via Same Net" "5 MIL [DEFAULT]" "0 MIL" "5.00 MIL" "DRC ERROR CLASS/GND2" "[ThruVia] +VCORE (VIA18D8A28) (1264.0 4964.0)" "[Gnd2 Shape] +VCORE ((495.0 4840.0) (1455.0 6000.0))" list(1255.000000 4964.000000) nil)@@@list("kelly1_pan" "2015/09/04 14:25:22" nil "P143000035-PC" "n3-p5-p7ncn.20")@@@list("jennifer_hsu" "2015/09/07 11:45:33" nil "P143000039-PC" "n3-p5-p7ncn.20") | list("[Spacing] GND2" "88.Shape to Thru Via Same Net" "5 MIL [DEFAULT]" "0 MIL" "5.00 MIL" "DRC ERROR CLASS/GND2" "[ThruVia] +VCORE (VIA18D8A28) (1264.0 4942.0)" "[Gnd2 Shape] +VCORE ((495.0 4840.0) (1455.0 6000.0))" list(1255.000000 4942.000000) nil)@@@list("kelly1_pan" "2015/09/04 14:25:21" nil "P143000035-PC" "n3-p5-p7ncn.20")@@@list("jennifer_hsu" "2015/09/07 11:45:33" nil "P143000039-PC" "n3-p5-p7ncn.20") | list("[Spacing] GND2" "87.Shape to Thru Via Same Net" "5 MIL [DEFAULT]" "0 MIL" "5.00 MIL" "DRC ERROR CLASS/GND2" "[ThruVia] +VCORE (VIA18D8A28) (1264.0 4920.0)" "[Gnd2 Shape] +VCORE ((495.0 4840.0) (1455.0 6000.0))" list(1255.000000 4920.000000) nil)@@@list("kelly1_pan" "2015/09/04 14:25:20" nil "P143000035-PC" "n3-p5-p7ncn.20")@@@list("jennifer_hsu" "2015/09/07 11:45:32" nil "P143000039-PC" "n3-p5-p7ncn.20") | list("[Spacing] GND2" "86.Shape to Thru Via Same Net" "5 MIL [DEFAULT]" "0 MIL" "5.00 MIL" "DRC ERROR CLASS/GND2" "[ThruVia] +VCORE (VIA18D8A28) (1264.0 4896.0)" "[Gnd2 Shape] +VCORE ((495.0 4840.0) (1455.0 6000.0))" list(1255.000000 4896.000000) nil)@@@list("kelly1_pan" "2015/09/04 14:25:20" nil "P143000035-PC" "n3-p5-p7ncn.20")@@@list("jennifer_hsu" "2015/09/07 11:45:31" nil "P143000039-PC" "n3-p5-p7ncn.20") | list("[Spacing] GND2" "49.Shape to Thru Via" "5 MIL [DEFAULT]" "0 MIL" "5.00 MIL" "DRC ERROR CLASS/GND2" "[ThruVia] +VCORE (VIA18D8A28) (1264.0 4964.0)" "[Gnd2 Shape] GND ((-917.01 -373.7) (9771.34 6936.7))" list(1265.000000 4972.940000) nil)@@@list("kelly1_pan" "2015/09/02 15:33:12" nil "P143000035-PC" "n3-p5-p7ncn.20")@@@list("jennifer_hsu" "2015/09/07 11:44:46" nil "P143000039-PC" "n3-p5-p7ncn.20") | list("[Spacing] GND2" "48.Shape to Thru Via" "5 MIL [DEFAULT]" "0 MIL" "5.00 MIL" "DRC ERROR CLASS/GND2" "[ThruVia] +VCORE (VIA18D8A28) (1264.0 4942.0)" "[Gnd2 Shape] GND ((-917.01 -373.7) (9771.34 6936.7))" list(1265.000000 4950.940000) nil)@@@list("kelly1_pan" "2015/09/02 15:33:11" nil "P143000035-PC" "n3-p5-p7ncn.20")@@@list("jennifer_hsu" "2015/09/07 11:44:45" nil "P143000039-PC" "n3-p5-p7ncn.20") | list("[Spacing] GND2" "47.Shape to Thru Via" "5 MIL [DEFAULT]" "0 MIL" "5.00 MIL" "DRC ERROR CLASS/GND2" "[ThruVia] +VCORE (VIA18D8A28) (1264.0 4920.0)" "[Gnd2 Shape] GND ((-917.01 -373.7) (9771.34 6936.7))" list(1265.000000 4928.940000) nil)@@@list("kelly1_pan" "2015/09/02 15:33:10" nil "P143000035-PC" "n3-p5-p7ncn.20")@@@list("jennifer_hsu" "2015/09/07 11:44:44" nil "P143000039-PC" "n3-p5-p7ncn.20") | list("[Spacing] GND2" "46.Shape to Thru Via" "5 MIL [DEFAULT]" "0 MIL" "5.00 MIL" "DRC ERROR CLASS/GND2" "[ThruVia] +VCORE (VIA18D8A28) (1264.0 4896.0)" "[Gnd2 Shape] GND ((-917.01 -373.7) (9771.34 6936.7))" list(1265.000000 4904.940000) nil)@@@list("kelly1_pan" "2015/09/02 15:33:09" nil "P143000035-PC" "n3-p5-p7ncn.20")@@@list("jennifer_hsu" "2015/09/07 11:44:43" nil "P143000039-PC" "n3-p5-p7ncn.20") | list("[Spacing] GND2" "73.Shape to Route Keepout" "0 MIL [DEFAULT]" "0 MIL" "0.00 MIL" "DRC ERROR CLASS/GND2" "[Shape] Route Keepout/All ((1831.32 6634.59) (1885.01 6688.27))" "[Gnd2 Shape] GND ((-917.01 -373.7) (9771.34 6936.7))" list(1885.010000 6661.430000) nil)@@@list("kelly1_pan" "2015/09/02 15:34:27" nil "P143000035-PC" "n3-p5-p7ncn.20")@@@list("jennifer_hsu" "2015/09/07 11:45:18" nil "P143000039-PC" "n3-p5-p7ncn.20") | list("[Spacing] GND2" "90.Shape to Thru Via" "5 MIL [DEFAULT]" "0 MIL" "5.00 MIL" "DRC ERROR CLASS/GND2" "[ThruVia] +3VO (VIA20D10A30) (2071.0 5973.0)" "[Gnd2 Shape] +VCCSA ((1225.0 5375.0) (2075.0 6220.0))" list(2070.930000 5983.000000) nil)@@@list("kelly1_pan" "2015/09/04 14:25:23" nil "P143000035-PC" "n3-p5-p7ncn.20")@@@list("jennifer_hsu" "2015/09/07 11:45:35" nil "P143000039-PC" "n3-p5-p7ncn.20") | list("[Spacing] GND2" "57.Shape to Thru Via" "5 MIL [DEFAULT]" "0 MIL" "5.00 MIL" "DRC ERROR CLASS/GND2" "[ThruVia] +3VO (VIA20D10A30) (2071.0 5973.0)" "[Gnd2 Shape] GND ((-917.01 -373.7) (9771.34 6936.7))" list(2079.810000 5977.730000) nil)@@@list("kelly1_pan" "2015/09/02 15:33:21" nil "P143000035-PC" "n3-p5-p7ncn.20")@@@list("jennifer_hsu" "2015/09/07 11:44:58" nil "P143000039-PC" "n3-p5-p7ncn.20") | list("[Spacing] GND2" "84.Shape to Thru Via Same Net" "5 MIL [DEFAULT]" "0 MIL" "5.00 MIL" "DRC ERROR CLASS/GND2" "[ThruVia] +NVVDD (VIA18D8A28) (2917.6 5805.9)" "[Gnd2 Shape] +NVVDD ((2620.0 3175.0) (4730.0 5916.89))" list(2921.850000 5797.970000) nil)@@@list("kelly1_pan" "2015/09/04 14:25:18" nil "P143000035-PC" "n3-p5-p7ncn.20")@@@list("jennifer_hsu" "2015/09/07 11:45:29" nil "P143000039-PC" "n3-p5-p7ncn.20") | list("[Spacing] GND2" "56.Shape to Thru Via" "5 MIL [DEFAULT]" "0 MIL" "5.00 MIL" "DRC ERROR CLASS/GND2" "[ThruVia] +NVVDD (VIA18D8A28) (2917.6 5805.9)" "[Gnd2 Shape] GND ((-917.01 -373.7) (9771.34 6936.7))" list(2926.450000 5807.510000) nil)@@@list("kelly1_pan" "2015/09/02 15:33:20" nil "P143000035-PC" "n3-p5-p7ncn.20")@@@list("jennifer_hsu" "2015/09/07 11:44:57" nil "P143000039-PC" "n3-p5-p7ncn.20") | list("[Spacing] GND2" "69.Shape to Route Keepout" "0 MIL [DEFAULT]" "0 MIL" "0.00 MIL" "DRC ERROR CLASS/GND2" "[Shape] Route Keepout/All ((2944.88 2456.7) (3007.88 2519.7))" "[Gnd2 Shape] GND ((-917.01 -373.7) (9771.34 6936.7))" list(2944.880000 2488.200000) nil)@@@list("kelly1_pan" "2015/09/02 15:33:31" nil "P143000035-PC" "n3-p5-p7ncn.20")@@@list("jennifer_hsu" "2015/09/07 11:45:07" nil "P143000039-PC" "n3-p5-p7ncn.20") | list("[Spacing] GND2" "66.Shape to Route Keepout" "0 MIL [DEFAULT]" "0 MIL" "0.00 MIL" "DRC ERROR CLASS/GND2" "[Shape] Route Keepout/All ((2944.88 1984.25) (3007.88 2047.25))" "[Gnd2 Shape] GND ((-917.01 -373.7) (9771.34 6936.7))" list(2944.880000 2015.750000) nil)@@@list("kelly1_pan" "2015/09/02 15:33:28" nil "P143000035-PC" "n3-p5-p7ncn.20")@@@list("jennifer_hsu" "2015/09/07 11:45:04" nil "P143000039-PC" "n3-p5-p7ncn.20") | list("[Spacing] GND2" "83.Shape to Thru Via Same Net" "5 MIL [DEFAULT]" "0 MIL" "5.00 MIL" "DRC ERROR CLASS/GND2" "[ThruVia] +NVVDD (VIA18D8A28) (2950.0 5775.0)" "[Gnd2 Shape] +NVVDD ((2620.0 3175.0) (4730.0 5916.89))" list(2953.220000 5766.590000) nil)@@@list("kelly1_pan" "2015/09/04 14:25:18" nil "P143000035-PC" "n3-p5-p7ncn.20")@@@list("jennifer_hsu" "2015/09/07 11:45:28" nil "P143000039-PC" "n3-p5-p7ncn.20") | list("[Spacing] GND2" "55.Shape to Thru Via" "5 MIL [DEFAULT]" "0 MIL" "5.00 MIL" "DRC ERROR CLASS/GND2" "[ThruVia] +NVVDD (VIA18D8A28) (2950.0 5775.0)" "[Gnd2 Shape] GND ((-917.01 -373.7) (9771.34 6936.7))" list(2959.000000 5774.960000) nil)@@@list("kelly1_pan" "2015/09/02 15:33:18" nil "P143000035-PC" "n3-p5-p7ncn.20")@@@list("jennifer_hsu" "2015/09/07 11:44:56" nil "P143000039-PC" "n3-p5-p7ncn.20") | list("[Spacing] GND2" "44.Shape to Thru Via" "5 MIL [DEFAULT]" "0 MIL" "5.00 MIL" "DRC ERROR CLASS/GND2" "[ThruVia] +3V3_AON (VIA20D10A30) (3012.0 4196.89)" "[Gnd2 Shape] GND ((-917.01 -373.7) (9771.34 6936.7))" list(3010.000000 4206.690000) nil)@@@list("kelly1_pan" "2015/09/02 15:33:07" nil "P143000035-PC" "n3-p5-p7ncn.20")@@@list("jennifer_hsu" "2015/09/07 11:44:42" nil "P143000039-PC" "n3-p5-p7ncn.20") | list("[Spacing] GND2" "45.Shape to Thru Via" "5 MIL [DEFAULT]" "0 MIL" "5.00 MIL" "DRC ERROR CLASS/GND2" "[ThruVia] WARNING (VIA20D10A30) (3012.5 4172.0)" "[Gnd2 Shape] GND ((-917.01 -373.7) (9771.34 6936.7))" list(3010.000000 4181.680000) nil)@@@list("kelly1_pan" "2015/09/02 15:33:08" nil "P143000035-PC" "n3-p5-p7ncn.20")@@@list("jennifer_hsu" "2015/09/07 11:44:42" nil "P143000039-PC" "n3-p5-p7ncn.20") | list("[Spacing] GND2" "79.Shape to Thru Via" "5 MIL [DEFAULT]" "0 MIL" "5.00 MIL" "DRC ERROR CLASS/GND2" "[ThruVia] +3V3_AON (VIA20D10A30) (3012.0 4196.89)" "[Gnd2 Shape] +NVVDD ((2620.0 3175.0) (4730.0 5916.89))" list(3020.000000 4202.890000) nil)@@@list("kelly1_pan" "2015/09/04 14:25:14" nil "P143000035-PC" "n3-p5-p7ncn.20")@@@list("jennifer_hsu" "2015/09/07 11:45:23" nil "P143000039-PC" "n3-p5-p7ncn.20") | list("[Spacing] GND2" "80.Shape to Thru Via" "5 MIL [DEFAULT]" "0 MIL" "5.00 MIL" "DRC ERROR CLASS/GND2" "[ThruVia] WARNING (VIA20D10A30) (3012.5 4172.0)" "[Gnd2 Shape] +NVVDD ((2620.0 3175.0) (4730.0 5916.89))" list(3020.000000 4178.610000) nil)@@@list("kelly1_pan" "2015/09/04 14:25:15" nil "P143000035-PC" "n3-p5-p7ncn.20")@@@list("jennifer_hsu" "2015/09/07 11:45:24" nil "P143000039-PC" "n3-p5-p7ncn.20") | list("[Spacing] GND2" "51.Shape to Thru Via Same Net" "5 MIL [DEFAULT]" "0 MIL" "5.00 MIL" "DRC ERROR CLASS/GND2" "[ThruVia] GND (VIA18D8A28) (3074.87 5681.14)" "[Gnd2 Shape] GND ((-917.01 -373.7) (9771.34 6936.7))" list(3065.900000 5681.890000) nil)@@@list("kelly1_pan" "2015/09/02 15:33:15" nil "P143000035-PC" "n3-p5-p7ncn.20")@@@list("jennifer_hsu" "2015/09/07 11:44:52" nil "P143000039-PC" "n3-p5-p7ncn.20") | list("[Spacing] GND2" "82.Shape to Thru Via" "5 MIL [DEFAULT]" "0.45 MIL" "4.55 MIL" "DRC ERROR CLASS/GND2" "[ThruVia] GND (VIA18D8A28) (3074.87 5681.14)" "[Gnd2 Shape] +NVVDD ((2620.0 3175.0) (4730.0 5916.89))" list(3073.020000 5672.330000) nil)@@@list("kelly1_pan" "2015/09/04 14:25:17" nil "P143000035-PC" "n3-p5-p7ncn.20")@@@list("jennifer_hsu" "2015/09/07 11:45:27" nil "P143000039-PC" "n3-p5-p7ncn.20") | list("[Spacing] GND2" "81.Shape to Thru Via" "5 MIL [DEFAULT]" "0 MIL" "5.00 MIL" "DRC ERROR CLASS/GND2" "[ThruVia] GND (VIA18D8A28) (3696.0 5546.0)" "[Gnd2 Shape] +NVVDD ((2620.0 3175.0) (4730.0 5916.89))" list(3687.990000 5541.890000) nil)@@@list("kelly1_pan" "2015/09/04 14:25:16" nil "P143000035-PC" "n3-p5-p7ncn.20")@@@list("jennifer_hsu" "2015/09/07 11:45:26" nil "P143000039-PC" "n3-p5-p7ncn.20") | list("[Spacing] GND2" "50.Shape to Thru Via Same Net" "5 MIL [DEFAULT]" "0 MIL" "5.00 MIL" "DRC ERROR CLASS/GND2" "[ThruVia] GND (VIA18D8A28) (3696.0 5546.0)" "[Gnd2 Shape] GND ((-917.01 -373.7) (9771.34 6936.7))" list(3702.800000 5551.890000) nil)@@@list("kelly1_pan" "2015/09/02 15:33:13" nil "P143000035-PC" "n3-p5-p7ncn.20")@@@list("jennifer_hsu" "2015/09/07 11:44:52" nil "P143000039-PC" "n3-p5-p7ncn.20") | list("[Spacing] GND2" "39.Shape to Route Keepout" "0 MIL [DEFAULT]" "0 MIL" "0.00 MIL" "DRC ERROR CLASS/GND2" "[Shape] Route Keepout/All ((6858.43 5535.43) (6984.05 5622.05))" "[Gnd2 Shape] GND_D-MIC R ((6566.9 5303.47) (7357.95 5617.8))" list(6883.030000 5617.800000) nil)@@@list("kelly1_pan" "2015/09/02 15:33:02" nil "P143000035-PC" "n3-p5-p7ncn.20")@@@list("jennifer_hsu" "2015/09/07 11:44:38" nil "P143000039-PC" "n3-p5-p7ncn.20") | list("[Spacing] GND2" "70.Shape to Route Keepout" "0 MIL [DEFAULT]" "0 MIL" "0.00 MIL" "DRC ERROR CLASS/GND2" "[Shape] Route Keepout/All ((8281.64 3112.35) (8348.26 3178.97))" "[Gnd2 Shape] GND ((-917.01 -373.7) (9771.34 6936.7))" list(8348.260000 3145.660000) nil)@@@list("kelly1_pan" "2015/09/02 15:33:32" nil "P143000035-PC" "n3-p5-p7ncn.20")@@@list("jennifer_hsu" "2015/09/07 11:45:07" nil "P143000039-PC" "n3-p5-p7ncn.20") | list("[Spacing] GND2" "63.Shape to Route Keepout" "0 MIL [DEFAULT]" "0 MIL" "0.00 MIL" "DRC ERROR CLASS/GND2" "[Shape] Route Keepout/All ((8396.75 1692.04) (8469.37 1764.66))" "[Gnd2 Shape] GND ((-917.01 -373.7) (9771.34 6936.7))" list(8469.370000 1728.350000) nil)@@@list("kelly1_pan" "2015/09/02 15:33:26" nil "P143000035-PC" "n3-p5-p7ncn.20")@@@list("jennifer_hsu" "2015/09/07 11:45:02" nil "P143000039-PC" "n3-p5-p7ncn.20") | list("[Spacing] GND2" "72.Shape to Route Keepout" "0 MIL [DEFAULT]" "0 MIL" "0.00 MIL" "DRC ERROR CLASS/GND2" "[Shape] Route Keepout/All ((8775.0 4660.0) (9725.0 5506.4))" "[Gnd2 Shape] GND ((-917.01 -373.7) (9771.34 6936.7))" list(9288.480000 5461.360000) nil)@@@list("kelly1_pan" "2015/09/02 15:33:34" nil "P143000035-PC" "n3-p5-p7ncn.20")@@@list("jennifer_hsu" "2015/09/07 11:45:08" nil "P143000039-PC" "n3-p5-p7ncn.20") | list("[Spacing] GND2" "40.Shape to Route Keepout" "0 MIL [DEFAULT]" "0 MIL" "0.00 MIL" "DRC ERROR CLASS/GND2" "[Shape] Route Keepout/All ((8775.0 4660.0) (9725.0 5506.4))" "[Gnd2 Shape] LAN_GND ((8795.0 4680.0) (9698.5 5487.0))" list(9289.360000 4680.000000) nil)@@@list("kelly1_pan" "2015/09/02 15:33:03" nil "P143000035-PC" "n3-p5-p7ncn.20")@@@list("jennifer_hsu" "2015/09/07 11:44:39" nil "P143000039-PC" "n3-p5-p7ncn.20") | list("[Spacing] GND2" "41.Shape to Route Keepin" "0 MIL [DEFAULT]" "0 MIL" "0.00 MIL" "DRC ERROR CLASS/GND2" "[Shape] Route Keepin/All ((-917.01 -373.7) (9771.34 6936.7))" "[Gnd2 Shape] LAN_GND ((8795.0 4680.0) (9698.5 5487.0))" list(9386.640000 5421.580000) nil)@@@list("kelly1_pan" "2015/09/02 15:33:04" nil "P143000035-PC" "n3-p5-p7ncn.20")@@@list("jennifer_hsu" "2015/09/07 11:44:39" nil "P143000039-PC" "n3-p5-p7ncn.20") | list("[Spacing] GND2" "74.Shape to Route Keepin" "0 MIL [DEFAULT]" "0 MIL" "0.00 MIL" "DRC ERROR CLASS/GND2" "[Shape] Route Keepin/All ((-917.01 -373.7) (9771.34 6936.7))" "[Gnd2 Shape] GND ((-917.01 -373.7) (9771.34 6936.7))" list(9433.500000 4571.180000) nil)@@@list("kelly1_pan" "2015/09/02 15:36:57" nil "P143000035-PC" "n3-p5-p7ncn.20")@@@list("jennifer_hsu" "2015/09/07 11:45:19" nil "P143000039-PC" "n3-p5-p7ncn.20") | list("[Spacing] GND2" "60.Shape to Route Keepout" "0 MIL [DEFAULT]" "0 MIL" "0.00 MIL" "DRC ERROR CLASS/GND2" "[Shape] Route Keepout/All ((9541.88 463.15) (9595.9 517.17))" "[Gnd2 Shape] GND ((-917.01 -373.7) (9771.34 6936.7))" list(9595.900000 490.160000) nil)@@@list("kelly1_pan" "2015/09/02 15:33:23" nil "P143000035-PC" "n3-p5-p7ncn.20")@@@list("jennifer_hsu" "2015/09/07 11:45:00" nil "P143000039-PC" "n3-p5-p7ncn.20")
